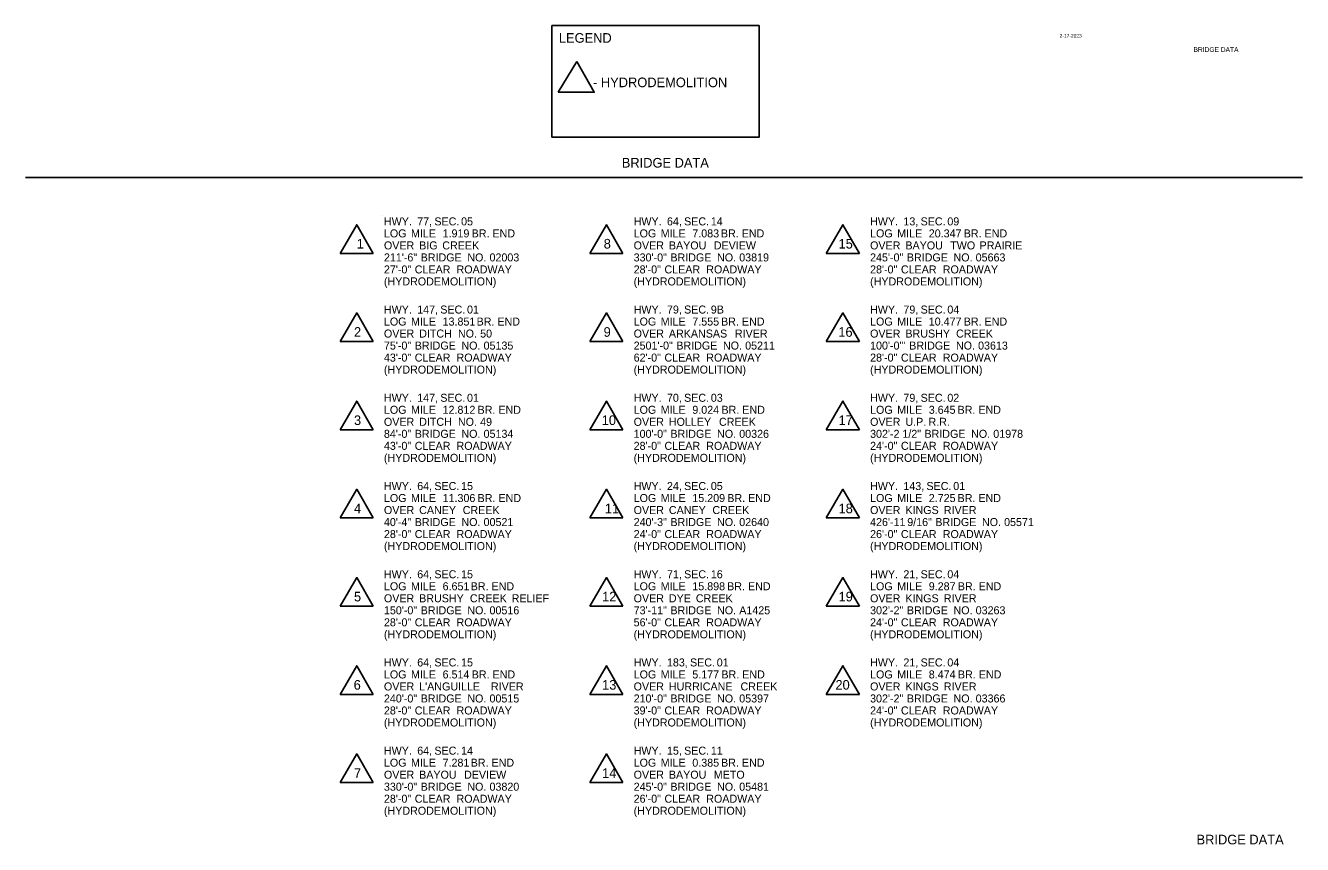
# Model space of a CAD drawing. Extents: x 1930546 to 1932142, y 596452 to 599553.
import ezdxf

# ---------------------------------------------------------------- set-up
doc = ezdxf.new("R2010")
doc.units = 0
for name, color, linetype in [('Default', 7, 'Continuous'), ('R_Border', 7, 'Continuous'), ('R_Border Prem', 7, 'Continuous')]:
    doc.layers.add(name, color=color, linetype=linetype)

msp = doc.modelspace()

# ---------------------------------------------------------------- linework, layer by layer
at = {"layer": 'R_Border'}
for p, q in [((1931235.2, 599508.3), (1931211.8, 599469.9)), ((1932141.6, 599363.5), (1930546.2, 599363.5)), ((1930992.1, 599315.7), (1930992.1, 599315.7)), ((1930939.3, 599268.8), (1930980.6, 599268.8)), ((1931251.3, 599268.8), (1931292.6, 599268.8)), ((1931546.7, 599268.8), (1931588.1, 599268.8)), ((1930939.3, 599158.7), (1930980.6, 599158.7)), ((1931251.3, 599158.7), (1931292.6, 599158.7)), ((1931546.7, 599158.7), (1931588.1, 599158.7)), ((1930939.3, 599048.5), (1930980.6, 599048.5)), ((1931251.3, 599048.5), (1931292.6, 599048.5)), ((1931546.7, 599048.5), (1931588.1, 599048.5)), ((1930939.3, 598938.3), (1930980.6, 598938.3)), ((1931251.3, 598938.3), (1931292.6, 598938.3)), ((1931546.7, 598938.3), (1931588.1, 598938.3)), ((1930939.3, 598828.1), (1930980.6, 598828.1)), ((1931251.3, 598828.1), (1931292.6, 598828.1)), ((1931546.7, 598828.1), (1931588.1, 598828.1)), ((1930939.3, 598718), (1930980.6, 598718)), ((1931251.3, 598718), (1931292.6, 598718)), ((1931546.7, 598718), (1931588.1, 598718)), ((1930939.3, 598607.8), (1930980.6, 598607.8)), ((1931251.3, 598607.8), (1931292.6, 598607.8))]:
    msp.add_line(p, q, dxfattribs=at)
msp.add_lwpolyline([(1931203.8, 599553.3), (1931462.7, 599553.3), (1931462.7, 599413.8), (1931203.8, 599413.8)], close=True, dxfattribs=at)
for points in [[(1931211.8, 599469.9), (1931256.8, 599469.9), (1931235.2, 599508.3)], [(1930980.6, 599268.8), (1930960, 599304.6), (1930939.3, 599268.8)], [(1931292.6, 599268.8), (1931272, 599304.6), (1931251.3, 599268.8)], [(1931588.1, 599268.8), (1931567.4, 599304.6), (1931546.7, 599268.8)], [(1930980.6, 599158.7), (1930960, 599194.4), (1930939.3, 599158.7)], [(1931292.6, 599158.7), (1931272, 599194.4), (1931251.3, 599158.7)], [(1931588.1, 599158.7), (1931567.4, 599194.4), (1931546.7, 599158.7)], [(1930980.6, 599048.5), (1930960, 599084.3), (1930939.3, 599048.5)], [(1931292.6, 599048.5), (1931272, 599084.3), (1931251.3, 599048.5)], [(1931588.1, 599048.5), (1931567.4, 599084.3), (1931546.7, 599048.5)], [(1930980.6, 598938.3), (1930960, 598974.1), (1930939.3, 598938.3)], [(1931292.6, 598938.3), (1931272, 598974.1), (1931251.3, 598938.3)], [(1931588.1, 598938.3), (1931567.4, 598974.1), (1931546.7, 598938.3)], [(1930980.6, 598828.1), (1930960, 598863.9), (1930939.3, 598828.1)], [(1931292.6, 598828.1), (1931272, 598863.9), (1931251.3, 598828.1)], [(1931588.1, 598828.1), (1931567.4, 598863.9), (1931546.7, 598828.1)], [(1930980.6, 598718), (1930960, 598753.7), (1930939.3, 598718)], [(1931292.6, 598718), (1931272, 598753.7), (1931251.3, 598718)], [(1931588.1, 598718), (1931567.4, 598753.7), (1931546.7, 598718)], [(1930980.6, 598607.8), (1930960, 598643.6), (1930939.3, 598607.8)], [(1931292.6, 598607.8), (1931272, 598643.6), (1931251.3, 598607.8)]]:
    msp.add_lwpolyline(points, dxfattribs=at)

# ---------------------------------------------------------------- texts
at = {"layer": 'Default'}
for s, p in [('HWY.', (1930994, 599303.7)), (' 77,', (1931031.9, 599303.7)), (' SEC.', (1931053.3, 599303.7)), (' 05', (1931086.7, 599303.7)), ('HWY.', (1931306, 599303.7)), (' 64,', (1931343.9, 599303.7)), (' SEC.', (1931365.3, 599303.7)), (' 14', (1931398.7, 599303.7)), ('HWY.', (1931601.4, 599303.7)), (' 13,', (1931639.3, 599303.7)), (' SEC.', (1931660.8, 599303.7)), (' 09', (1931694.2, 599303.7)), ('LOG', (1930994, 599288.7)), (' MILE', (1931024.1, 599288.7)), (' 1.919', (1931063.6, 599288.7)), (' BR.', (1931099.9, 599288.7)), (' END', (1931125.9, 599288.7)), ('LOG', (1931306, 599288.7)), (' MILE', (1931336.1, 599288.7)), (' 7.083', (1931375.6, 599288.7)), (' BR.', (1931411.3, 599288.7)), (' END', (1931437.3, 599288.7)), ('LOG', (1931601.4, 599288.7)), (' MILE', (1931631.6, 599288.7)), (' 20.347', (1931671, 599288.7)), (' BR.', (1931714.7, 599288.7)), (' END', (1931740.7, 599288.7)), ('OVER', (1930994, 599273.7)), (' BIG', (1931034.3, 599273.7)), (' CREEK', (1931063.2, 599273.7)), ('OVER', (1931306, 599273.7)), (' BAYOU', (1931346.3, 599273.7)), (' DEVIEW', (1931402.4, 599273.7)), ('OVER', (1931601.4, 599273.7)), (' BAYOU', (1931641.8, 599273.7)), (' TWO', (1931697.8, 599273.7)), (' PRAIRIE', (1931734.5, 599273.7)), ('211\'-6"', (1930994, 599258.7)), (' BRIDGE', (1931036.2, 599258.7)), (' NO.', (1931094.5, 599258.7)), (' 02003', (1931122.2, 599258.7)), ('330\'-0"', (1931306, 599258.7)), (' BRIDGE', (1931348.2, 599258.7)), (' NO.', (1931406.5, 599258.7)), (' 03819', (1931434.2, 599258.7)), ('245\'-0"', (1931601.4, 599258.7)), (' BRIDGE', (1931643.6, 599258.7)), (' NO.', (1931701.9, 599258.7)), (' 05663', (1931729.6, 599258.7)), ('27\'-0"', (1930994, 599243.7)), (' CLEAR', (1931028.8, 599243.7)), (' ROADWAY', (1931081, 599243.7)), ('28\'-0"', (1931306, 599243.7)), (' CLEAR', (1931340.8, 599243.7)), (' ROADWAY', (1931393, 599243.7)), ('28\'-0"', (1931601.4, 599243.7)), (' CLEAR', (1931636.2, 599243.7)), (' ROADWAY', (1931688.5, 599243.7)), ('(HYDRODEMOLITION)', (1930994, 599228.7)), ('(HYDRODEMOLITION)', (1931306, 599228.7)), ('(HYDRODEMOLITION)', (1931601.4, 599228.7)), ('HWY.', (1930994, 599193.6)), (' 147,', (1931031.9, 599193.6)), (' SEC.', (1931060.7, 599193.6)), (' 01', (1931094.1, 599193.6)), ('HWY.', (1931306, 599193.6)), (' 79,', (1931343.9, 599193.6)), (' SEC.', (1931365.3, 599193.6)), (' 9B', (1931398.7, 599193.6)), ('HWY.', (1931601.4, 599193.6)), (' 79,', (1931639.3, 599193.6)), (' SEC.', (1931660.8, 599193.6)), (' 04', (1931694.2, 599193.6)), ('LOG', (1930994, 599178.6)), (' MILE', (1931024.1, 599178.6)), (' 13.851', (1931063.6, 599178.6)), (' BR.', (1931106.1, 599178.6)), (' END', (1931132.1, 599178.6)), ('LOG', (1931306, 599178.6)), (' MILE', (1931336.1, 599178.6)), (' 7.555', (1931375.6, 599178.6)), (' BR.', (1931411.5, 599178.6)), (' END', (1931437.6, 599178.6)), ('LOG', (1931601.4, 599178.6)), (' MILE', (1931631.6, 599178.6)), (' 10.477', (1931671, 599178.6)), (' BR.', (1931714.7, 599178.6)), (' END', (1931740.7, 599178.6)), ('OVER', (1930994, 599163.6)), (' DITCH', (1931034.3, 599163.6)), (' NO.', (1931082.8, 599163.6)), (' 50', (1931110.5, 599163.6)), ('OVER', (1931306, 599163.6)), (' ARKANSAS', (1931346.3, 599163.6)), (' RIVER', (1931428.8, 599163.6)), ('OVER', (1931601.4, 599163.6)), (' BRUSHY', (1931641.8, 599163.6)), (' CREEK', (1931705.1, 599163.6)), ('75\'-0"', (1930994, 599148.6)), (' BRIDGE', (1931028.8, 599148.6)), (' NO.', (1931087.1, 599148.6)), (' 05135', (1931114.8, 599148.6)), ('2501\'-0"', (1931306, 599148.6)), (' BRIDGE', (1931355.6, 599148.6)), (' NO.', (1931413.9, 599148.6)), (' 05211', (1931441.6, 599148.6)), ('100\'-0"\'', (1931601.4, 599148.6)), (' BRIDGE', (1931646.6, 599148.6)), (' NO.', (1931705, 599148.6)), (' 03613', (1931732.6, 599148.6)), ('43\'-0"', (1930994, 599133.6)), (' CLEAR', (1931028.8, 599133.6)), (' ROADWAY', (1931081, 599133.6)), ('62\'-0"', (1931306, 599133.6)), (' CLEAR', (1931340.8, 599133.6)), (' ROADWAY', (1931393, 599133.6)), ('28\'-0"', (1931601.4, 599133.6)), (' CLEAR', (1931636.2, 599133.6)), (' ROADWAY', (1931688.5, 599133.6)), ('(HYDRODEMOLITION)', (1930994, 599118.6)), ('(HYDRODEMOLITION)', (1931306, 599118.6)), ('(HYDRODEMOLITION)', (1931601.4, 599118.6)), ('HWY.', (1930994, 599083.4)), (' 147,', (1931031.9, 599083.4)), (' SEC.', (1931060.7, 599083.4)), (' 01', (1931094.1, 599083.4)), ('HWY.', (1931306, 599083.4)), (' 70,', (1931343.9, 599083.4)), (' SEC.', (1931365.3, 599083.4)), (' 03', (1931398.7, 599083.4)), ('HWY.', (1931601.4, 599083.4)), (' 79,', (1931639.3, 599083.4)), (' SEC.', (1931660.8, 599083.4)), (' 02', (1931694.2, 599083.4)), ('LOG', (1930994, 599068.4)), (' MILE', (1931024.1, 599068.4)), (' 12.812', (1931063.6, 599068.4)), (' BR.', (1931107.3, 599068.4)), (' END', (1931133.3, 599068.4)), ('LOG', (1931306, 599068.4)), (' MILE', (1931336.1, 599068.4)), (' 9.024', (1931375.6, 599068.4)), (' BR.', (1931412, 599068.4)), (' END', (1931438, 599068.4)), ('LOG', (1931601.4, 599068.4)), (' MILE', (1931631.6, 599068.4)), (' 3.645', (1931671, 599068.4)), (' BR.', (1931707, 599068.4)), (' END', (1931733, 599068.4)), ('OVER', (1930994, 599053.4)), (' DITCH', (1931034.3, 599053.4)), (' NO.', (1931082.8, 599053.4)), (' 49', (1931110.5, 599053.4)), ('OVER', (1931306, 599053.4)), (' HOLLEY', (1931346.3, 599053.4)), (' CREEK', (1931408.9, 599053.4)), ('OVER', (1931601.4, 599053.4)), (' U.P.', (1931641.8, 599053.4)), (' R.R.', (1931670.7, 599053.4)), ('84\'-0"', (1930994, 599038.4)), (' BRIDGE', (1931028.8, 599038.4)), (' NO.', (1931087.1, 599038.4)), (' 05134', (1931114.8, 599038.4)), ('100\'-0"', (1931306, 599038.4)), (' BRIDGE', (1931348.2, 599038.4)), (' NO.', (1931406.5, 599038.4)), (' 00326', (1931434.2, 599038.4)), ("302'-2", (1931601.4, 599038.4)), (' 1/2"', (1931638, 599038.4)), (' BRIDGE', (1931665.6, 599038.4)), (' NO.', (1931723.9, 599038.4)), (' 01978', (1931751.6, 599038.4)), ('43\'-0"', (1930994, 599023.4)), (' CLEAR', (1931028.8, 599023.4)), (' ROADWAY', (1931081, 599023.4)), ('28\'-0"', (1931306, 599023.4)), (' CLEAR', (1931340.8, 599023.4)), (' ROADWAY', (1931393, 599023.4)), ('24\'-0"', (1931601.4, 599023.4)), (' CLEAR', (1931636.2, 599023.4)), (' ROADWAY', (1931688.5, 599023.4)), ('(HYDRODEMOLITION)', (1930994, 599008.4)), ('(HYDRODEMOLITION)', (1931306, 599008.4)), ('(HYDRODEMOLITION)', (1931601.4, 599008.4)), ('HWY.', (1930994, 598973.2)), (' 64,', (1931031.9, 598973.2)), (' SEC.', (1931053.3, 598973.2)), (' 15', (1931086.7, 598973.2)), ('HWY.', (1931306, 598973.2)), (' 24,', (1931343.9, 598973.2)), (' SEC.', (1931365.3, 598973.2)), (' 05', (1931398.7, 598973.2)), ('HWY.', (1931601.4, 598973.2)), (' 143,', (1931639.3, 598973.2)), (' SEC.', (1931668.1, 598973.2)), (' 01', (1931701.6, 598973.2)), ('LOG', (1930994, 598958.2)), (' MILE', (1931024.1, 598958.2)), (' 11.306', (1931063.6, 598958.2)), (' BR.', (1931107.3, 598958.2)), (' END', (1931133.4, 598958.2)), ('LOG', (1931306, 598958.2)), (' MILE', (1931336.1, 598958.2)), (' 15.209', (1931375.6, 598958.2)), (' BR.', (1931419.3, 598958.2)), (' END', (1931445.3, 598958.2)), ('LOG', (1931601.4, 598958.2)), (' MILE', (1931631.6, 598958.2)), (' 2.725', (1931671, 598958.2)), (' BR.', (1931707, 598958.2)), (' END', (1931733, 598958.2)), ('OVER', (1930994, 598943.2)), (' CANEY', (1931034.3, 598943.2)), (' CREEK', (1931088.7, 598943.2)), ('OVER', (1931306, 598943.2)), (' CANEY', (1931346.3, 598943.2)), (' CREEK', (1931400.7, 598943.2)), ('OVER', (1931601.4, 598943.2)), (' KINGS', (1931641.8, 598943.2)), (' RIVER', (1931689.8, 598943.2)), ('40\'-4"', (1930994, 598928.2)), (' BRIDGE', (1931028.8, 598928.2)), (' NO.', (1931087.1, 598928.2)), (' 00521', (1931114.8, 598928.2)), ('240\'-3"', (1931306, 598928.2)), (' BRIDGE', (1931348.2, 598928.2)), (' NO.', (1931406.5, 598928.2)), (' 02640', (1931434.2, 598928.2)), ("426'-11", (1931601.4, 598928.2)), (' 9/16"', (1931644.1, 598928.2)), (' BRIDGE', (1931679.2, 598928.2)), (' NO.', (1931737.5, 598928.2)), (' 05571', (1931765.1, 598928.2)), ('28\'-0"', (1930994, 598913.2)), (' CLEAR', (1931028.8, 598913.2)), (' ROADWAY', (1931081, 598913.2)), ('24\'-0"', (1931306, 598913.2)), (' CLEAR', (1931340.8, 598913.2)), (' ROADWAY', (1931393, 598913.2)), ('26\'-0"', (1931601.4, 598913.2)), (' CLEAR', (1931636.2, 598913.2)), (' ROADWAY', (1931688.5, 598913.2)), ('(HYDRODEMOLITION)', (1930994, 598898.2)), ('(HYDRODEMOLITION)', (1931306, 598898.2)), ('(HYDRODEMOLITION)', (1931601.4, 598898.2)), ('HWY.', (1930994, 598863)), (' 64,', (1931031.9, 598863)), (' SEC.', (1931053.3, 598863)), (' 15', (1931086.7, 598863)), ('HWY.', (1931306, 598863)), (' 71,', (1931343.9, 598863)), (' SEC.', (1931365.3, 598863)), (' 16', (1931398.7, 598863)), ('HWY.', (1931601.4, 598863)), (' 21,', (1931639.3, 598863)), (' SEC.', (1931660.8, 598863)), (' 04', (1931694.2, 598863)), ('LOG', (1930994, 598848)), (' MILE', (1931024.1, 598848)), (' 6.651', (1931063.6, 598848)), (' BR.', (1931098.7, 598848)), (' END', (1931124.7, 598848)), ('LOG', (1931306, 598848)), (' MILE', (1931336.1, 598848)), (' 15.898', (1931375.6, 598848)), (' BR.', (1931419.1, 598848)), (' END', (1931445.1, 598848)), ('LOG', (1931601.4, 598848)), (' MILE', (1931631.6, 598848)), (' 9.287', (1931671, 598848)), (' BR.', (1931707.3, 598848)), (' END', (1931733.3, 598848)), ('OVER', (1930994, 598833)), (' BRUSHY', (1931034.3, 598833)), (' CREEK', (1931097.7, 598833)), (' RELIEF', (1931149.9, 598833)), ('OVER', (1931306, 598833)), (' DYE', (1931346.3, 598833)), (' CREEK', (1931380, 598833)), ('OVER', (1931601.4, 598833)), (' KINGS', (1931641.8, 598833)), (' RIVER', (1931689.8, 598833)), ('150\'-0"', (1930994, 598818)), (' BRIDGE', (1931036.2, 598818)), (' NO.', (1931094.5, 598818)), (' 00516', (1931122.2, 598818)), ('73\'-11"', (1931306, 598818)), (' BRIDGE', (1931348.2, 598818)), (' NO.', (1931406.5, 598818)), (' A1425', (1931434.2, 598818)), ('302\'-2"', (1931601.4, 598818)), (' BRIDGE', (1931643.6, 598818)), (' NO.', (1931701.9, 598818)), (' 03263', (1931729.6, 598818)), ('28\'-0"', (1930994, 598803)), (' CLEAR', (1931028.8, 598803)), (' ROADWAY', (1931081, 598803)), ('56\'-0"', (1931306, 598803)), (' CLEAR', (1931340.8, 598803)), (' ROADWAY', (1931393, 598803)), ('24\'-0"', (1931601.4, 598803)), (' CLEAR', (1931636.2, 598803)), (' ROADWAY', (1931688.5, 598803)), ('(HYDRODEMOLITION)', (1930994, 598788)), ('(HYDRODEMOLITION)', (1931306, 598788)), ('(HYDRODEMOLITION)', (1931601.4, 598788)), ('HWY.', (1930994, 598752.9)), (' 64,', (1931031.9, 598752.9)), (' SEC.', (1931053.3, 598752.9)), (' 15', (1931086.7, 598752.9)), ('HWY.', (1931306, 598752.9)), (' 183,', (1931343.9, 598752.9)), (' SEC.', (1931372.7, 598752.9)), (' 01', (1931406.1, 598752.9)), ('HWY.', (1931601.4, 598752.9)), (' 21,', (1931639.3, 598752.9)), (' SEC.', (1931660.8, 598752.9)), (' 04', (1931694.2, 598752.9)), ('LOG', (1930994, 598737.9)), (' MILE', (1931024.1, 598737.9)), (' 6.514', (1931063.6, 598737.9)), (' BR.', (1931100, 598737.9)), (' END', (1931126, 598737.9)), ('LOG', (1931306, 598737.9)), (' MILE', (1931336.1, 598737.9)), (' 5.177', (1931375.6, 598737.9)), (' BR.', (1931411.9, 598737.9)), (' END', (1931437.9, 598737.9)), ('LOG', (1931601.4, 598737.9)), (' MILE', (1931631.6, 598737.9)), (' 8.474', (1931671, 598737.9)), (' BR.', (1931707.4, 598737.9)), (' END', (1931733.5, 598737.9)), ('OVER', (1930994, 598722.9)), (" L'ANGUILLE", (1931034.3, 598722.9)), (' RIVER', (1931124, 598722.9)), ('OVER', (1931306, 598722.9)), (' HURRICANE', (1931346.3, 598722.9)), (' CREEK', (1931435.8, 598722.9)), ('OVER', (1931601.4, 598722.9)), (' KINGS', (1931641.8, 598722.9)), (' RIVER', (1931689.8, 598722.9)), ('240\'-0"', (1930994, 598707.9)), (' BRIDGE', (1931036.2, 598707.9)), (' NO.', (1931094.5, 598707.9)), (' 00515', (1931122.2, 598707.9)), ('210\'-0"', (1931306, 598707.9)), (' BRIDGE', (1931348.2, 598707.9)), (' NO.', (1931406.5, 598707.9)), (' 05397', (1931434.2, 598707.9)), ('302\'-2"', (1931601.4, 598707.9)), (' BRIDGE', (1931643.6, 598707.9)), (' NO.', (1931701.9, 598707.9)), (' 03366', (1931729.6, 598707.9)), ('28\'-0"', (1930994, 598692.9)), (' CLEAR', (1931028.8, 598692.9)), (' ROADWAY', (1931081, 598692.9)), ('39\'-0"', (1931306, 598692.9)), (' CLEAR', (1931340.8, 598692.9)), (' ROADWAY', (1931393, 598692.9)), ('24\'-0"', (1931601.4, 598692.9)), (' CLEAR', (1931636.2, 598692.9)), (' ROADWAY', (1931688.5, 598692.9)), ('(HYDRODEMOLITION)', (1930994, 598677.9)), ('(HYDRODEMOLITION)', (1931306, 598677.9)), ('(HYDRODEMOLITION)', (1931601.4, 598677.9)), ('HWY.', (1930994, 598642.7)), (' 64,', (1931031.9, 598642.7)), (' SEC.', (1931053.3, 598642.7)), (' 14', (1931086.7, 598642.7)), ('HWY.', (1931306, 598642.7)), (' 15,', (1931343.9, 598642.7)), (' SEC.', (1931365.3, 598642.7)), (' 11', (1931398.7, 598642.7)), ('LOG', (1930994, 598627.7)), (' MILE', (1931024.1, 598627.7)), (' 7.281', (1931063.6, 598627.7)), (' BR.', (1931098.7, 598627.7)), (' END', (1931124.7, 598627.7)), ('LOG', (1931306, 598627.7)), (' MILE', (1931336.1, 598627.7)), (' 0.385', (1931375.6, 598627.7)), (' BR.', (1931411.5, 598627.7)), (' END', (1931437.6, 598627.7)), ('OVER', (1930994, 598612.7)), (' BAYOU', (1931034.3, 598612.7)), (' DEVIEW', (1931090.4, 598612.7)), ('OVER', (1931306, 598612.7)), (' BAYOU', (1931346.3, 598612.7)), (' METO', (1931402.4, 598612.7)), ('330\'-0"', (1930994, 598597.7)), (' BRIDGE', (1931036.2, 598597.7)), (' NO.', (1931094.5, 598597.7)), (' 03820', (1931122.2, 598597.7)), ('245\'-0"', (1931306, 598597.7)), (' BRIDGE', (1931348.2, 598597.7)), (' NO.', (1931406.5, 598597.7)), (' 05481', (1931434.2, 598597.7)), ('28\'-0"', (1930994, 598582.7)), ('(HYDRODEMOLITION)', (1930994, 598567.7)), (' CLEAR', (1931028.8, 598582.7)), (' ROADWAY', (1931081, 598582.7)), ('26\'-0"', (1931306, 598582.7)), ('(HYDRODEMOLITION)', (1931306, 598567.7)), (' CLEAR', (1931340.8, 598582.7)), (' ROADWAY', (1931393, 598582.7))]:
    msp.add_text(s, height=10, dxfattribs=at).set_placement(p)
at = {"layer": 'R_Border'}
for s, p in [('LEGEND', (1931212.6, 599531.8)), ('- HYDRODEMOLITION', (1931255.3, 599476.3)), ('BRIDGE DATA', (1931291.2, 599375.9)), ('1', (1930960, 599274.8)), ('8', (1931268.6, 599274.8)), ('15', (1931562, 599274.8)), ('2', (1930956.6, 599164.6)), ('9', (1931268.5, 599164.6)), ('16', (1931561.7, 599164.6)), ('3', (1930956.6, 599054.4)), ('10', (1931266.1, 599054.4)), ('17', (1931562, 599054.4)), ('4', (1930956.6, 598944.2)), ('11', (1931270, 598944.2)), ('18', (1931562, 598944.2)), ('5', (1930956.6, 598834.1)), ('12', (1931266.6, 598834.1)), ('19', (1931562, 598834.1)), ('6', (1930956.2, 598723.9)), ('13', (1931266.6, 598723.9)), ('20', (1931558.1, 598723.9)), ('7', (1930956.6, 598613.7)), ('14', (1931266.6, 598613.7)), ('BRIDGE DATA', (1932009.3, 598530.7))]:
    msp.add_text(s, height=12, rotation=360, dxfattribs=at).set_placement(p)
at = {"layer": 'R_Border Prem'}
msp.add_text('2-17-2023', height=4.4, dxfattribs=at).set_placement((1931838.2, 599538.2))
msp.add_text('BRIDGE DATA', height=6, rotation=360, dxfattribs=at).set_placement((1932005.5, 599520.3))

doc.saveas('drawing.dxf')
